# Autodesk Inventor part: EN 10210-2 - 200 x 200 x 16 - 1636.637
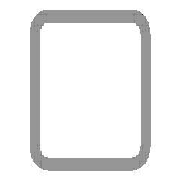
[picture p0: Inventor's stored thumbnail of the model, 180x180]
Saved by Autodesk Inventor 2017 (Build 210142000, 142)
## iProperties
_CCFamilyMember: 94
_CCFamilyDisplayName: DIN EN 10210-2 (Square) - Tube — Sizes in parentheses have been withdrawn
_FrameMemberDoc: Frame Member File
_Version: 15.0.0
_GetPNFromCC: 1
Created: 2017-11
Part Number: EN 10210-2 - 200 x 200 x 16 - 1636.637
Material: Steel, Mild
Description: Tube
Document SubType Name: Modeling
Standard: DIN
Designer: iusti
Standard Revision: 2006-07
Standards Organization: DIN
Language: en-US
Size Designation: 200 x 200 x 16
Categories: <MemberInstance><Categories><Category DisplayName="Structural Shapes" InternalName="089c4875-fa83-4c05-b084-43b9cc11f5ed" Mnemonic="GRDR"><CategoryParameter Dis
Stock Number: 200 x 200 x 16
Density: 7.85 g/cm^3
Appearance: Semi-Polished
Mass: 135428 g
Surface Area: 21335.1 cm^2
Volume: 17252 cm^3
IsCustomPart: 1
G_L: 1636.637 mm
G_W: 200.000 mm
G_H: 200.000 mm
+987C6673-447C-412A-9B24-0CD20188E66E+CUTDETAIL1: Miter 69.88 deg
+D0655DDE-97F9-4B99-A490-E36C02108510+CUTDETAIL2: Miter 45.00 deg
Author: iusti
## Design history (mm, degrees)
node "Start plane"
node "End plane"
sketch "Sketch"
  geometry: L1 (-100, -76)-(-100, 76); L2 (-76, 100)-(76, 100); L3 (100, 76)-(100, -76); L4 (76, -100)-(-76, -100); L5 (-68, 84)-(68, 84); L6 (84, 68)-(84, -68); L7 (68, -84)-(-68, -84); L8 (-84, -68)-(-84, 68); L9 (0, 146.959)-(0, -146.959) reference; L10 (-146.959, 0)-(146.959, 0) reference; A1 r 24 centre (-76, -76) between (-100, -76) and (-76, -100); A2 r 24 centre (-76, 76) between (-76, 100) and (-100, 76); A3 r 24 centre (76, 76) between (100, 76) and (76, 100); A4 r 24 centre (76, -76) between (76, -100) and (100, -76); A5 r 16 centre (-68, -68) between (-84, -68) and (-68, -84); A6 r 16 centre (-68, 68) between (-68, 84) and (-84, 68); A7 r 16 centre (68, 68) between (84, 68) and (68, 84); A8 r 16 centre (68, -68) between (68, -84) and (84, -68)
  constraints: 16 end point, 16 point on circle, 16 tangent, 8 centre point, 6 equal radius, 4 parallel, 2 perpendicular, 2 other
  dimensions: "d7" = 24 radius of A1 (= G_IR); "d10" = 200 distance between parallel lines of L2 L4 (= G_H); "d11" = 200 distance between parallel lines of L1 L3 (= G_W); "d12" = 16 distance between parallel lines of L3 L6 (= G_T); "d15" = 100 distance between parallel lines of L2 L10 (= 0.5 x d10); "d16" = 100 distance between parallel lines of L9 L3 (= 0.5 x d11); "d19" = 16 radius of A5 (= G_T); "d20" = 16 distance between parallel lines of L4 L7 (= G_T)
extrude "Body" new body sketch "Sketch" stored distance "d3" = 1636.6372 (= G_L); taper "d4" = 0 deg
node "Driven Length"
  sketch "Sketch3"
    geometry: L1 (0, 0)-(10, 0) reference
    constraints: 2 end point, 1 horizontal
  workplane "Work Plane3"
  sketch "Sketch4"
    geometry: L1 (-2, -36.637)-(12, -36.637) reference; L2 (-2, 1600)-(12, 1600) reference
    dimensions: "d18" = 1636.6372 distance between parallel lines of L1 L2 (derived)
workplane "Work Plane4"
split "Split1"
workplane "Work Plane5"
split "Split2"
body "Solid1"
other parameters: "G_W" = 200 [user parameter; used in 1 equation term], "G_H" = 200 [user parameter; used in 1 equation term], "G_T" = 16 [user parameter; used in 3 equation terms], "G_IR" = 24 [user parameter; used in 1 equation term], "G_L" = 1636.6372 (= d18) [user parameter; used in 1 equation term], "G_OFFSET_START" = 36.6372 [user parameter; used in 1 equation term], "d13" = -36.6372 (= -G_OFFSET_START), "d17" = 90 deg
